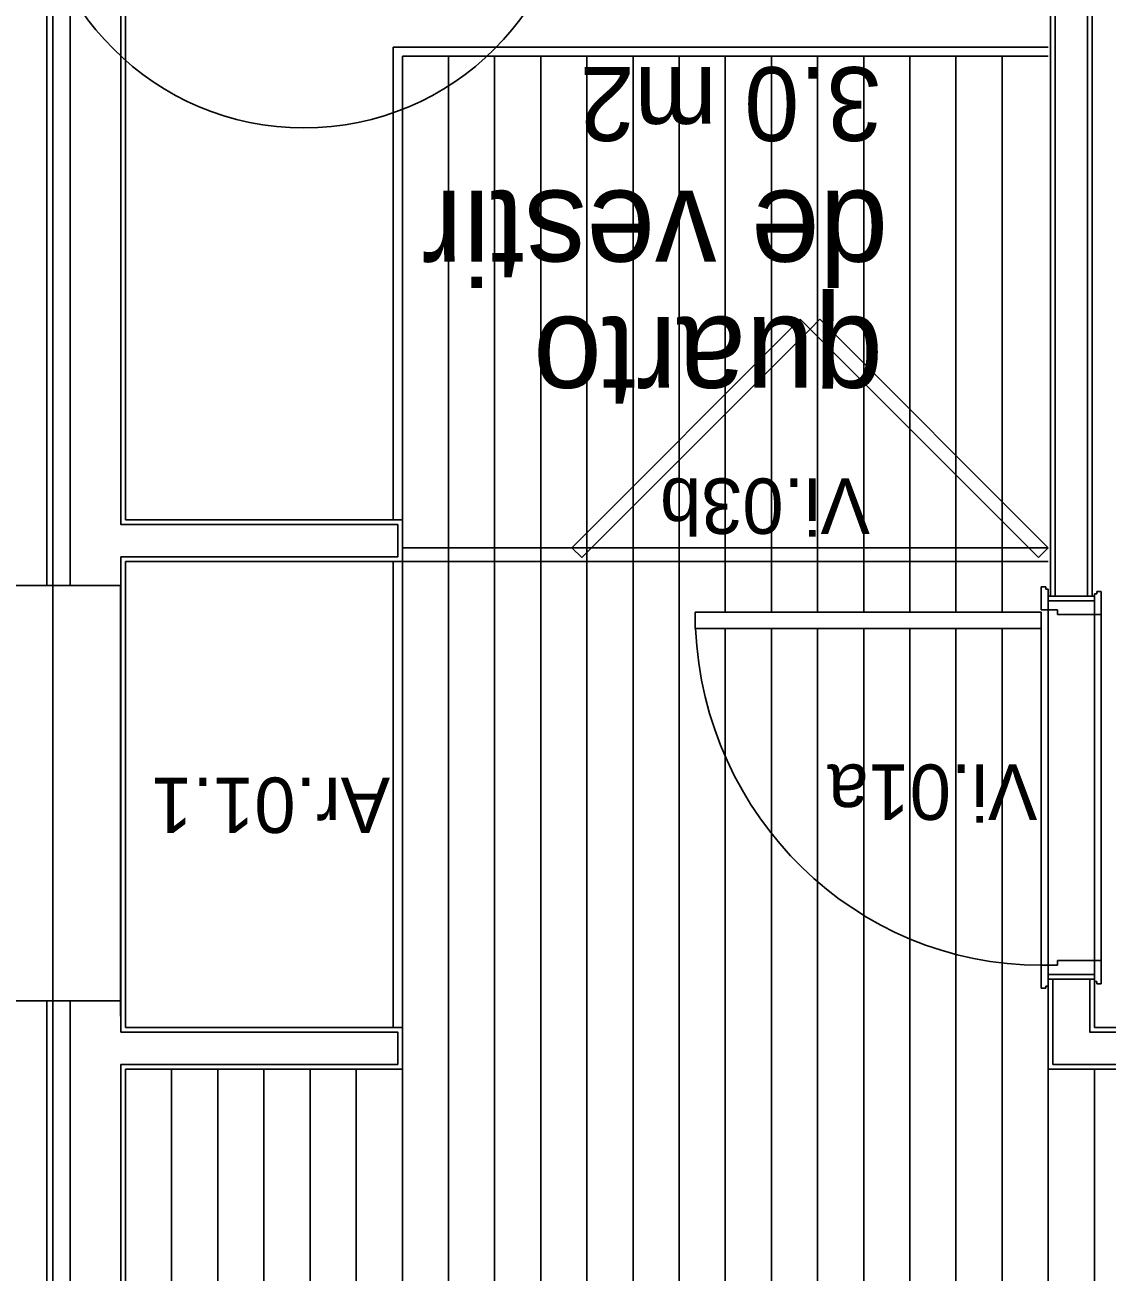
# Model space of a CAD drawing. Extents: x 1278 to 1356, y -253.7 to -224.
# Drawn here: x 1323.824 to 1326.169, y -243.659 to -240.956 of the extents above; entities that cross this region are included whole.
import ezdxf

# ---------------------------------------------------------------- set-up
doc = ezdxf.new("R2010")
doc.units = 0
for name, color, linetype in [('Level 1', 7, 'Continuous'), ('Level 10', 7, 'Continuous'), ('Level 13', 7, 'Continuous'), ('Level 4', 7, 'Continuous'), ('Level 40', 7, 'Continuous'), ('Level 60', 7, 'Continuous'), ('Level 65', 7, 'Continuous'), ('Level 66', 7, 'Continuous'), ('Level 67', 7, 'Continuous'), ('Level 69', 7, 'Continuous'), ('Level 70', 7, 'Continuous')]:
    doc.layers.add(name, color=color, linetype=linetype)

msp = doc.modelspace()

# ---------------------------------------------------------------- linework, layer by layer
at = {"layer": 'Level 1'}
for p, q in [((1324.0318, -242.039), (1324.0317, -232.2657)), ((1323.871, -236.7713), (1323.871, -242.1713)), ((1323.9218, -242.1713), (1323.9218, -236.7713)), ((1326.0568, -240.414), (1326.0568, -242.194)), ((1326.1268, -242.194), (1326.1268, -240.414)), ((1324.6318, -242.109), (1324.6318, -242.039)), ((1324.0318, -243.134), (1324.0318, -242.109)), ((1326.0418, -242.194), (1326.1418, -242.194)), ((1326.0418, -243.219), (1326.0418, -243.024)), ((1326.0418, -243.024), (1326.1418, -243.024)), ((1326.0518, -243.209), (1326.0518, -243.024)), ((1326.1318, -243.024), (1326.1318, -243.139)), ((1323.871, -243.0713), (1323.871, -245.8713)), ((1323.9218, -245.8713), (1323.9218, -243.0713)), ((1324.0318, -243.139), (1324.0318, -243.134)), ((1324.6318, -243.139), (1324.0318, -243.139)), ((1324.6318, -243.209), (1324.6318, -243.139)), ((1326.1318, -243.139), (1327.0518, -243.139)), ((1324.0318, -243.209), (1324.6318, -243.209)), ((1324.0318, -246.584), (1324.0318, -243.209)), ((1326.5568, -243.209), (1326.0518, -243.209))]:
    msp.add_line(p, q, dxfattribs=at)
at = {"layer": 'Level 10'}
for p, q in [((1324.7418, -246.574), (1324.7418, -241.024)), ((1324.8418, -246.574), (1324.8418, -241.024)), ((1324.9418, -246.574), (1324.9418, -241.024)), ((1325.0418, -246.574), (1325.0418, -241.024)), ((1325.1418, -246.574), (1325.1418, -241.024)), ((1325.2418, -246.574), (1325.2418, -241.024)), ((1325.3418, -242.229), (1325.3418, -241.024)), ((1325.4418, -242.229), (1325.4418, -241.024)), ((1325.5418, -242.229), (1325.5418, -241.024)), ((1325.6418, -242.229), (1325.6418, -241.024)), ((1325.7418, -242.229), (1325.7418, -241.024)), ((1325.8418, -242.229), (1325.8418, -241.024)), ((1325.9418, -242.229), (1325.9418, -241.024)), ((1326.0418, -242.994), (1326.0418, -242.224)), ((1326.1418, -242.984), (1326.1418, -242.234)), ((1325.3418, -246.574), (1325.3418, -242.264)), ((1325.4418, -246.574), (1325.4418, -242.264)), ((1325.5418, -246.574), (1325.5418, -242.264)), ((1325.6418, -246.574), (1325.6418, -242.264)), ((1325.7418, -246.574), (1325.7418, -242.264)), ((1325.8418, -246.574), (1325.8418, -242.264)), ((1325.9418, -246.574), (1325.9418, -242.264)), ((1324.1418, -246.574), (1324.1418, -243.219)), ((1324.2418, -246.574), (1324.2418, -243.219)), ((1324.3418, -246.574), (1324.3418, -243.219)), ((1324.4418, -246.574), (1324.4418, -243.219)), ((1324.5418, -246.574), (1324.5418, -243.219)), ((1324.6418, -246.574), (1324.6418, -243.219)), ((1326.0418, -243.219), (1326.0418, -246.574)), ((1326.1418, -243.219), (1326.1418, -246.574))]:
    msp.add_line(p, q, dxfattribs=at)
at = {"layer": 'Level 13'}
for p, q in [((1326.0418, -241.004), (1324.6218, -241.004)), ((1324.6218, -241.004), (1324.6218, -242.029)), ((1326.0418, -241.024), (1324.6418, -241.024)), ((1324.6418, -241.024), (1324.6418, -242.029)), ((1325.0094, -242.089), (1325.5044, -241.594)), ((1325.5044, -241.594), (1325.5256, -241.6152)), ((1325.5468, -241.594), (1325.5256, -241.6152)), ((1326.0418, -242.089), (1325.5468, -241.594)), ((1325.0306, -242.1102), (1325.5256, -241.6152)), ((1326.0206, -242.1102), (1325.5256, -241.6152)), ((1325.0094, -242.089), (1325.0306, -242.1102)), ((1326.0418, -242.089), (1326.0206, -242.1102)), ((1324.6218, -242.119), (1324.6218, -243.129)), ((1324.6418, -242.119), (1324.6418, -243.129)), ((1326.0268, -242.174), (1326.0268, -242.224)), ((1326.0368, -242.174), (1326.0268, -242.174)), ((1326.0368, -242.179), (1326.0368, -242.174)), ((1326.0418, -242.179), (1326.0368, -242.179)), ((1326.0418, -242.224), (1326.0418, -242.179)), ((1326.0418, -242.204), (1326.1418, -242.204)), ((1326.0418, -242.224), (1326.0418, -242.204)), ((1326.1418, -242.234), (1326.1418, -242.189)), ((1326.1418, -242.189), (1326.1468, -242.189)), ((1326.1418, -242.204), (1326.1418, -242.234)), ((1326.1468, -242.189), (1326.1468, -242.184)), ((1326.1468, -242.184), (1326.1568, -242.184)), ((1326.1568, -242.184), (1326.1568, -242.234)), ((1325.2768, -242.229), (1326.0268, -242.229)), ((1325.2768, -242.264), (1325.2768, -242.229)), ((1326.0268, -242.224), (1326.0418, -242.224)), ((1326.0268, -242.229), (1326.0268, -242.264)), ((1326.0618, -242.224), (1326.0418, -242.224)), ((1326.0618, -242.234), (1326.0618, -242.224)), ((1326.1418, -242.234), (1326.0618, -242.234)), ((1326.1568, -242.234), (1326.1418, -242.234)), ((1326.0268, -242.264), (1325.2768, -242.264)), ((1326.1418, -242.984), (1326.0618, -242.984)), ((1326.0618, -242.984), (1326.0618, -242.994)), ((1326.1418, -243.014), (1326.1418, -242.984)), ((1326.1568, -242.984), (1326.1418, -242.984)), ((1326.1418, -242.984), (1326.1418, -243.029)), ((1326.1568, -243.034), (1326.1568, -242.984)), ((1326.0268, -243.044), (1326.0268, -242.994)), ((1326.0268, -242.994), (1326.0418, -242.994)), ((1326.0418, -242.994), (1326.0418, -243.039)), ((1326.0618, -242.994), (1326.0418, -242.994)), ((1326.0418, -242.994), (1326.0418, -243.014)), ((1326.0418, -243.014), (1326.1418, -243.014)), ((1326.0368, -243.044), (1326.0268, -243.044)), ((1326.0418, -243.039), (1326.0368, -243.039)), ((1326.0368, -243.039), (1326.0368, -243.044)), ((1326.1418, -243.029), (1326.1468, -243.029)), ((1326.1468, -243.029), (1326.1468, -243.034)), ((1326.1468, -243.034), (1326.1568, -243.034))]:
    msp.add_line(p, q, dxfattribs=at)
at = {"layer": 'Level 4'}
for p, q in [((1324.6418, -242.089), (1326.0418, -242.089)), ((1324.6418, -242.119), (1326.0418, -242.119)), ((1326.1568, -242.234), (1326.1568, -242.984)), ((1326.0268, -242.994), (1326.0268, -242.264))]:
    msp.add_line(p, q, dxfattribs=at)
msp.add_ellipse((1326.0268, -242.2308), major_axis=(0, 0.7632), ratio=0.982661, start_param=1.614288, end_param=3.141593, dxfattribs=at)
at = {"layer": 'Level 65'}
for p, q in [((1326.0468, -240.424), (1326.0468, -242.194)), ((1326.1368, -242.194), (1326.1368, -240.424)), ((1324.0418, -242.029), (1324.0418, -240.6839)), ((1324.6418, -242.029), (1324.0418, -242.029)), ((1324.6418, -242.119), (1324.6418, -242.029)), ((1324.0418, -242.119), (1324.6418, -242.119)), ((1324.0418, -243.129), (1324.0418, -242.119)), ((1326.1418, -243.024), (1326.1418, -243.129)), ((1324.6418, -243.129), (1324.0418, -243.129)), ((1324.6418, -243.219), (1324.6418, -243.129)), ((1326.1418, -243.129), (1327.0418, -243.129)), ((1324.0418, -246.574), (1324.0418, -243.219)), ((1324.0418, -243.219), (1324.6418, -243.219)), ((1326.5468, -243.219), (1326.0418, -243.219))]:
    msp.add_line(p, q, dxfattribs=at)
at = {"layer": 'Level 66'}
for p, q in [((1324.6318, -242.039), (1324.0318, -242.039)), ((1324.6318, -242.109), (1324.0318, -242.109))]:
    msp.add_line(p, q, dxfattribs=at)
msp.add_lwpolyline([(1324.031, -243.0713), (1323.801, -243.0713), (1323.801, -242.1713), (1324.031, -242.1713)], close=True, dxfattribs=at)
at = {"layer": 'Level 67'}
for points in [[(1323.871, -242.1713), (1323.801, -242.1713), (1323.801, -236.7713), (1323.871, -236.7713), (1323.871, -242.1713)], [(1324.031, -242.1713), (1324.0318, -242.1713), (1324.0318, -242.109), (1324.6318, -242.109), (1324.6318, -242.039), (1324.0318, -242.039), (1324.031, -236.7713), (1323.9218, -236.7713), (1323.9218, -242.1713), (1324.0318, -242.1713)], [(1326.1268, -240.414), (1326.1268, -242.194), (1326.0568, -242.194), (1326.0568, -240.414)], [(1326.6268, -246.584), (1326.5568, -246.584), (1326.5568, -243.209), (1326.0518, -243.209), (1326.0518, -243.024), (1326.1318, -243.024), (1326.1318, -243.139), (1327.0518, -243.139), (1327.0518, -243.024), (1327.1318, -243.024), (1327.1318, -243.209), (1326.6268, -243.209)], [(1323.871, -243.0713), (1323.801, -243.0713), (1323.801, -245.8713), (1323.871, -245.8713)], [(1323.9218, -243.0713), (1323.9218, -245.8713), (1324.031, -245.8713), (1324.0318, -243.209), (1324.6318, -243.209), (1324.6318, -243.139), (1324.0318, -243.139), (1324.031, -243.0713)]]:
    msp.add_lwpolyline(points, close=True, dxfattribs=at)
at = {"layer": 'Level 69'}
msp.add_circle((1324.4286, -240.5951), 0.5842, dxfattribs=at)
msp.add_circle((1324.4286, -240.5951), 0.5842, dxfattribs=at)
at = {"layer": 'Level 70'}
msp.add_line((1323.884, -250.7923), (1323.884, -229.6198), dxfattribs=at)

# ---------------------------------------------------------------- texts
at = {"layer": 'Level 40'}
for s, p in [('Vi.03b', (1325.6553, -241.939)), ('Vi.01a', (1326.0181, -242.5589)), ('Ar.01.1', (1324.6153, -242.5872))]:
    msp.add_text(s, height=0.12, rotation=180, dxfattribs=at).set_placement(p)
at = {"layer": 'Level 60'}
for s, height, p in [('3.0 m2', 0.16, (1325.6804, -241.0475)), ('de vestir', 0.2, (1325.6947, -241.3153)), ('de vestir', 0.2, (1325.6947, -241.3153)), ('quarto', 0.2, (1325.6837, -241.5889))]:
    msp.add_text(s, height=height, rotation=180, dxfattribs=at).set_placement(p)

doc.saveas('drawing.dxf')
